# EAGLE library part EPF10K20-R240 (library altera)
EPF10K20 FLEX 10K family
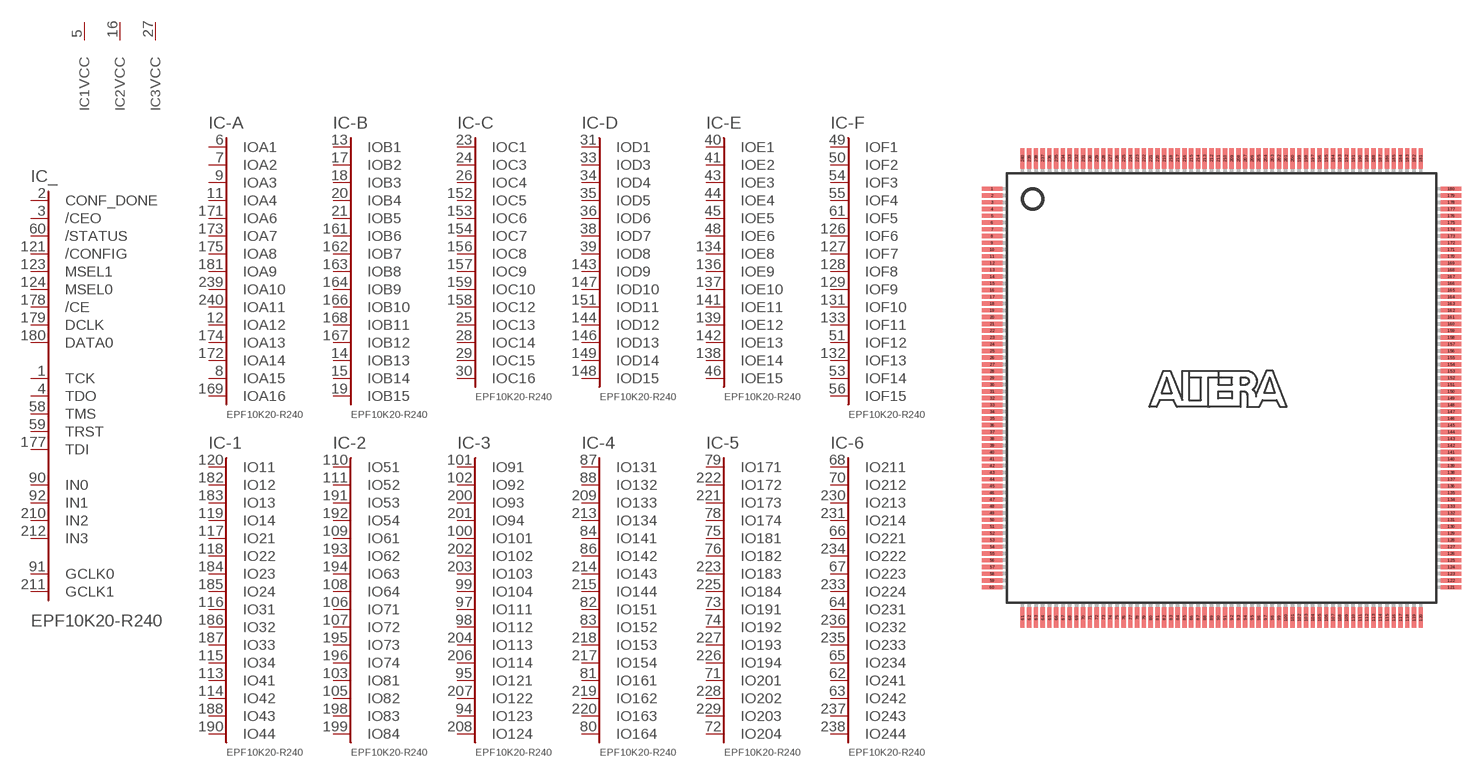
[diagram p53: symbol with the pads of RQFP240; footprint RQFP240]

Designator prefix IC; gates _=100R240C -A=A16-15 -B=B16-15 -C=C16-14 -D=D15-14 -E=E15-14 -F=F15 -1=IO44 -2=IO84 -3=IO124 -4=IO164 -5=IO204 -6=IO244 1=VCCINT 2=VCCINT 3=VCCINT 4=VCCINT 5=VCCINT 6=VCCINT 7=VCCINT 8=VCCINT 9=VCCINT 10=VCCINT 11=VCCINT 12=VCCINT 13=VCCINT 14=VCCINT 15=VCCINT 16=VCCINT 17=VCCINT 18=VCCINT 19=VCCINT 20=GNDINT 21=GNDINT 22=GNDINT 23=GNDINT 24=GNDINT 25=GNDINT 26=GNDINT 27=GNDINT 28=GNDINT 29=GNDINT 30=GNDINT 31=GNDINT 32=GNDINT 33=GNDINT 34=GNDINT 35=GNDINT 36=GNDINT 37=GNDINT

## EPF10K20-R240 (MPN: EPF10K20RC240-3N; OC_FARNELL: unknown; OC_NEWARK: 51R8884)  [RQFP240]
1  _:TCK
2  _:CONF_DONE  in
3  _:/CEO  in
4  _:TDO
5  1:VCC  pwr
6  -A:IOA1
7  -A:IOA2
8  -A:IOA15
9  -A:IOA3
10  20:GND  pwr
11  -A:IOA4
12  -A:IOA12
13  -B:IOB1
14  -B:IOB13
15  -B:IOB14
16  2:VCC  pwr
17  -B:IOB2
18  -B:IOB3
19  -B:IOB15
20  -B:IOB4
21  -B:IOB5
22  21:GND  pwr
23  -C:IOC1
24  -C:IOC3
25  -C:IOC13
26  -C:IOC4
27  3:VCC  pwr
28  -C:IOC14
29  -C:IOC15
30  -C:IOC16
31  -D:IOD1
32  22:GND  pwr
33  -D:IOD3
34  -D:IOD4
35  -D:IOD5
36  -D:IOD6
37  4:VCC  pwr
38  -D:IOD7
39  -D:IOD8
40  -E:IOE1
41  -E:IOE2
42  23:GND  pwr
43  -E:IOE3
44  -E:IOE4
45  -E:IOE5
46  -E:IOE15
47  5:VCC  pwr
48  -E:IOE6
49  -F:IOF1
50  -F:IOF2
51  -F:IOF12
52  24:GND  pwr
53  -F:IOF14
54  -F:IOF3
55  -F:IOF4
56  -F:IOF15
57  6:VCC  pwr
58  _:TMS
59  _:TRST
60  _:/STATUS  in
61  -F:IOF5
62  -6:IO241
63  -6:IO242
64  -6:IO231
65  -6:IO234
66  -6:IO221
67  -6:IO223
68  -6:IO211
69  25:GND  pwr
70  -6:IO212
71  -5:IO201
72  -5:IO204
73  -5:IO191
74  -5:IO192
75  -5:IO181
76  -5:IO182
77  7:VCC  pwr
78  -5:IO174
79  -5:IO171
80  -4:IO164
81  -4:IO161
82  -4:IO151
83  -4:IO152
84  -4:IO141
85  26:GND  pwr
86  -4:IO142
87  -4:IO131
88  -4:IO132
89  8:VCC  pwr
90  _:IN0  in
91  _:GCLK0  in
92  _:IN1  in
93  27:GND  pwr
94  -3:IO123
95  -3:IO121
96  9:VCC  pwr
97  -3:IO111
98  -3:IO112
99  -3:IO104
100  -3:IO101
101  -3:IO91
102  -3:IO92
103  -2:IO81
104  28:GND  pwr
105  -2:IO82
106  -2:IO71
107  -2:IO72
108  -2:IO64
109  -2:IO61
110  -2:IO51
111  -2:IO52
112  10:VCC  pwr
113  -1:IO41
114  -1:IO42
115  -1:IO34
116  -1:IO31
117  -1:IO21
118  -1:IO22
119  -1:IO14
120  -1:IO11
121  _:/CONFIG  in
122  11:VCC  pwr
123  _:MSEL1  in
124  _:MSEL0  in
125  29:GND  pwr
126  -F:IOF6
127  -F:IOF7
128  -F:IOF8
129  -F:IOF9
130  12:VCC  pwr
131  -F:IOF10
132  -F:IOF13
133  -F:IOF11
134  -E:IOE8
135  30:GND  pwr
136  -E:IOE9
137  -E:IOE10
138  -E:IOE14
139  -E:IOE12
140  13:VCC  pwr
141  -E:IOE11
142  -E:IOE13
143  -D:IOD9
144  -D:IOD12
145  31:GND  pwr
146  -D:IOD13
147  -D:IOD10
148  -D:IOD15
149  -D:IOD14
150  14:VCC  pwr
151  -D:IOD11
152  -C:IOC5
153  -C:IOC6
154  -C:IOC7
155  32:GND  pwr
156  -C:IOC8
157  -C:IOC9
158  -C:IOC12
159  -C:IOC10
160  15:VCC  pwr
161  -B:IOB6
162  -B:IOB7
163  -B:IOB8
164  -B:IOB9
165  33:GND  pwr
166  -B:IOB10
167  -B:IOB12
168  -B:IOB11
169  -A:IOA16
170  16:VCC  pwr
171  -A:IOA6
172  -A:IOA14
173  -A:IOA7
174  -A:IOA13
175  -A:IOA8
176  34:GND  pwr
177  _:TDI
178  _:/CE  in
179  _:DCLK  in
180  _:DATA0  in
181  -A:IOA9
182  -1:IO12
183  -1:IO13
184  -1:IO23
185  -1:IO24
186  -1:IO32
187  -1:IO33
188  -1:IO43
189  17:VCC  pwr
190  -1:IO44
191  -2:IO53
192  -2:IO54
193  -2:IO62
194  -2:IO63
195  -2:IO73
196  -2:IO74
197  35:GND  pwr
198  -2:IO83
199  -2:IO84
200  -3:IO93
201  -3:IO94
202  -3:IO102
203  -3:IO103
204  -3:IO113
205  18:VCC  pwr
206  -3:IO114
207  -3:IO122
208  -3:IO124
209  -4:IO133
210  _:IN2  in
211  _:GCLK1  in
212  _:IN3  in
213  -4:IO134
214  -4:IO143
215  -4:IO144
216  36:GND  pwr
217  -4:IO154
218  -4:IO153
219  -4:IO162
220  -4:IO163
221  -5:IO173
222  -5:IO172
223  -5:IO183
224  19:VCC  pwr
225  -5:IO184
226  -5:IO194
227  -5:IO193
228  -5:IO202
229  -5:IO203
230  -6:IO213
231  -6:IO214
232  37:GND  pwr
233  -6:IO224
234  -6:IO222
235  -6:IO233
236  -6:IO232
237  -6:IO243
238  -6:IO244
239  -A:IOA10
240  -A:IOA11

## Footprint RQFP240 (pad centres in mm)
Power Quad Flat Pack
smd 1.5 x 0.32: 1 -17,14.75; 2 -17,14.25; 3 -17,13.75; 4 -17,13.25; 5 -17,12.75; 6 -17,12.25; 7 -17,11.75; 8 -17,11.25; 9 -17,10.75; 10 -17,10.25; 11 -17,9.75; 12 -17,9.25; 13 -17,8.75; 14 -17,8.25; 15 -17,7.75; 16 -17,7.25; 17 -17,6.75; 18 -17,6.25; 19 -17,5.75; 20 -17,5.25; 21 -17,4.75; 22 -17,4.25; 23 -17,3.75; 24 -17,3.25; 25 -17,2.75; 26 -17,2.25; 27 -17,1.75; 28 -17,1.25; 29 -17,0.75; 30 -17,0.25; 31 -17,-0.25; 32 -17,-0.75; 33 -17,-1.25; 34 -17,-1.75; 35 -17,-2.25; 36 -17,-2.75; 37 -17,-3.25; 38 -17,-3.75; 39 -17,-4.25; 40 -17,-4.75; 41 -17,-5.25; 42 -17,-5.75; 43 -17,-6.25; 44 -17,-6.75; 45 -17,-7.25; 46 -17,-7.75; 47 -17,-8.25; 48 -17,-8.75; 49 -17,-9.25; 50 -17,-9.75; 51 -17,-10.25; 52 -17,-10.75; 53 -17,-11.25; 54 -17,-11.75; 55 -17,-12.25; 56 -17,-12.75; 57 -17,-13.25; 58 -17,-13.75; 59 -17,-14.25; 60 -17,-14.75; 121 17,-14.75; 122 17,-14.25; 123 17,-13.75; 124 17,-13.25; 125 17,-12.75; 126 17,-12.25; 127 17,-11.75; 128 17,-11.25; 129 17,-10.75; 130 17,-10.25; 131 17,-9.75; 132 17,-9.25; 133 17,-8.75; 134 17,-8.25; 135 17,-7.75; 136 17,-7.25; 137 17,-6.75; 138 17,-6.25; 139 17,-5.75; 140 17,-5.25; 141 17,-4.75; 142 17,-4.25; 143 17,-3.75; 144 17,-3.25; 145 17,-2.75; 146 17,-2.25; 147 17,-1.75; 148 17,-1.25; 149 17,-0.75; 150 17,-0.25; 151 17,0.25; 152 17,0.75; 153 17,1.25; 154 17,1.75; 155 17,2.25; 156 17,2.75; 157 17,3.25; 158 17,3.75; 159 17,4.25; 160 17,4.75; 161 17,5.25; 162 17,5.75; 163 17,6.25; 164 17,6.75; 165 17,7.25; 166 17,7.75; 167 17,8.25; 168 17,8.75; 169 17,9.25; 170 17,9.75; 171 17,10.25; 172 17,10.75; 173 17,11.25; 174 17,11.75; 175 17,12.25; 176 17,12.75; 177 17,13.25; 178 17,13.75; 179 17,14.25; 180 17,14.75
smd 0.32 x 1.5: 61 -14.75,-17; 62 -14.25,-17; 63 -13.75,-17; 64 -13.25,-17; 65 -12.75,-17; 66 -12.25,-17; 67 -11.75,-17; 68 -11.25,-17; 69 -10.75,-17; 70 -10.25,-17; 71 -9.75,-17; 72 -9.25,-17; 73 -8.75,-17; 74 -8.25,-17; 75 -7.75,-17; 76 -7.25,-17; 77 -6.75,-17; 78 -6.25,-17; 79 -5.75,-17; 80 -5.25,-17; 81 -4.75,-17; 82 -4.25,-17; 83 -3.75,-17; 84 -3.25,-17; 85 -2.75,-17; 86 -2.25,-17; 87 -1.75,-17; 88 -1.25,-17; 89 -0.75,-17; 90 -0.25,-17; 91 0.25,-17; 92 0.75,-17; 93 1.25,-17; 94 1.75,-17; 95 2.25,-17; 96 2.75,-17; 97 3.25,-17; 98 3.75,-17; 99 4.25,-17; 100 4.75,-17; 101 5.25,-17; 102 5.75,-17; 103 6.25,-17; 104 6.75,-17; 105 7.25,-17; 106 7.75,-17; 107 8.25,-17; 108 8.75,-17; 109 9.25,-17; 110 9.75,-17; 111 10.25,-17; 112 10.75,-17; 113 11.25,-17; 114 11.75,-17; 115 12.25,-17; 116 12.75,-17; 117 13.25,-17; 118 13.75,-17; 119 14.25,-17; 120 14.75,-17; 181 14.75,17; 182 14.25,17; 183 13.75,17; 184 13.25,17; 185 12.75,17; 186 12.25,17; 187 11.75,17; 188 11.25,17; 189 10.75,17; 190 10.25,17; 191 9.75,17; 192 9.25,17; 193 8.75,17; 194 8.25,17; 195 7.75,17; 196 7.25,17; 197 6.75,17; 198 6.25,17; 199 5.75,17; 200 5.25,17; 201 4.75,17; 202 4.25,17; 203 3.75,17; 204 3.25,17; 205 2.75,17; 206 2.25,17; 207 1.75,17; 208 1.25,17; 209 0.75,17; 210 0.25,17; 211 -0.25,17; 212 -0.75,17; 213 -1.25,17; 214 -1.75,17; 215 -2.25,17; 216 -2.75,17; 217 -3.25,17; 218 -3.75,17; 219 -4.25,17; 220 -4.75,17; 221 -5.25,17; 222 -5.75,17; 223 -6.25,17; 224 -6.75,17; 225 -7.25,17; 226 -7.75,17; 227 -8.25,17; 228 -8.75,17; 229 -9.25,17; 230 -9.75,17; 231 -10.25,17; 232 -10.75,17; 233 -11.25,17; 234 -11.75,17; 235 -12.25,17; 236 -12.75,17; 237 -13.25,17; 238 -13.75,17; 239 -14.25,17; 240 -14.75,17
